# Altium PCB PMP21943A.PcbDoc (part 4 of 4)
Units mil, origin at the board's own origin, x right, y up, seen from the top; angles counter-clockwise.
Board outline 5100 x 3900 mil, 8 copper layers (Top Layer, Signal Layer 1, Signal Layer 2, Signal Layer 3, Signal Layer 4, Signal Layer 5, Signal Layer 6, Bottom Layer), stack 61.6 mil thick; 371 components, 163 nets, 967 pads, 1147 vias.
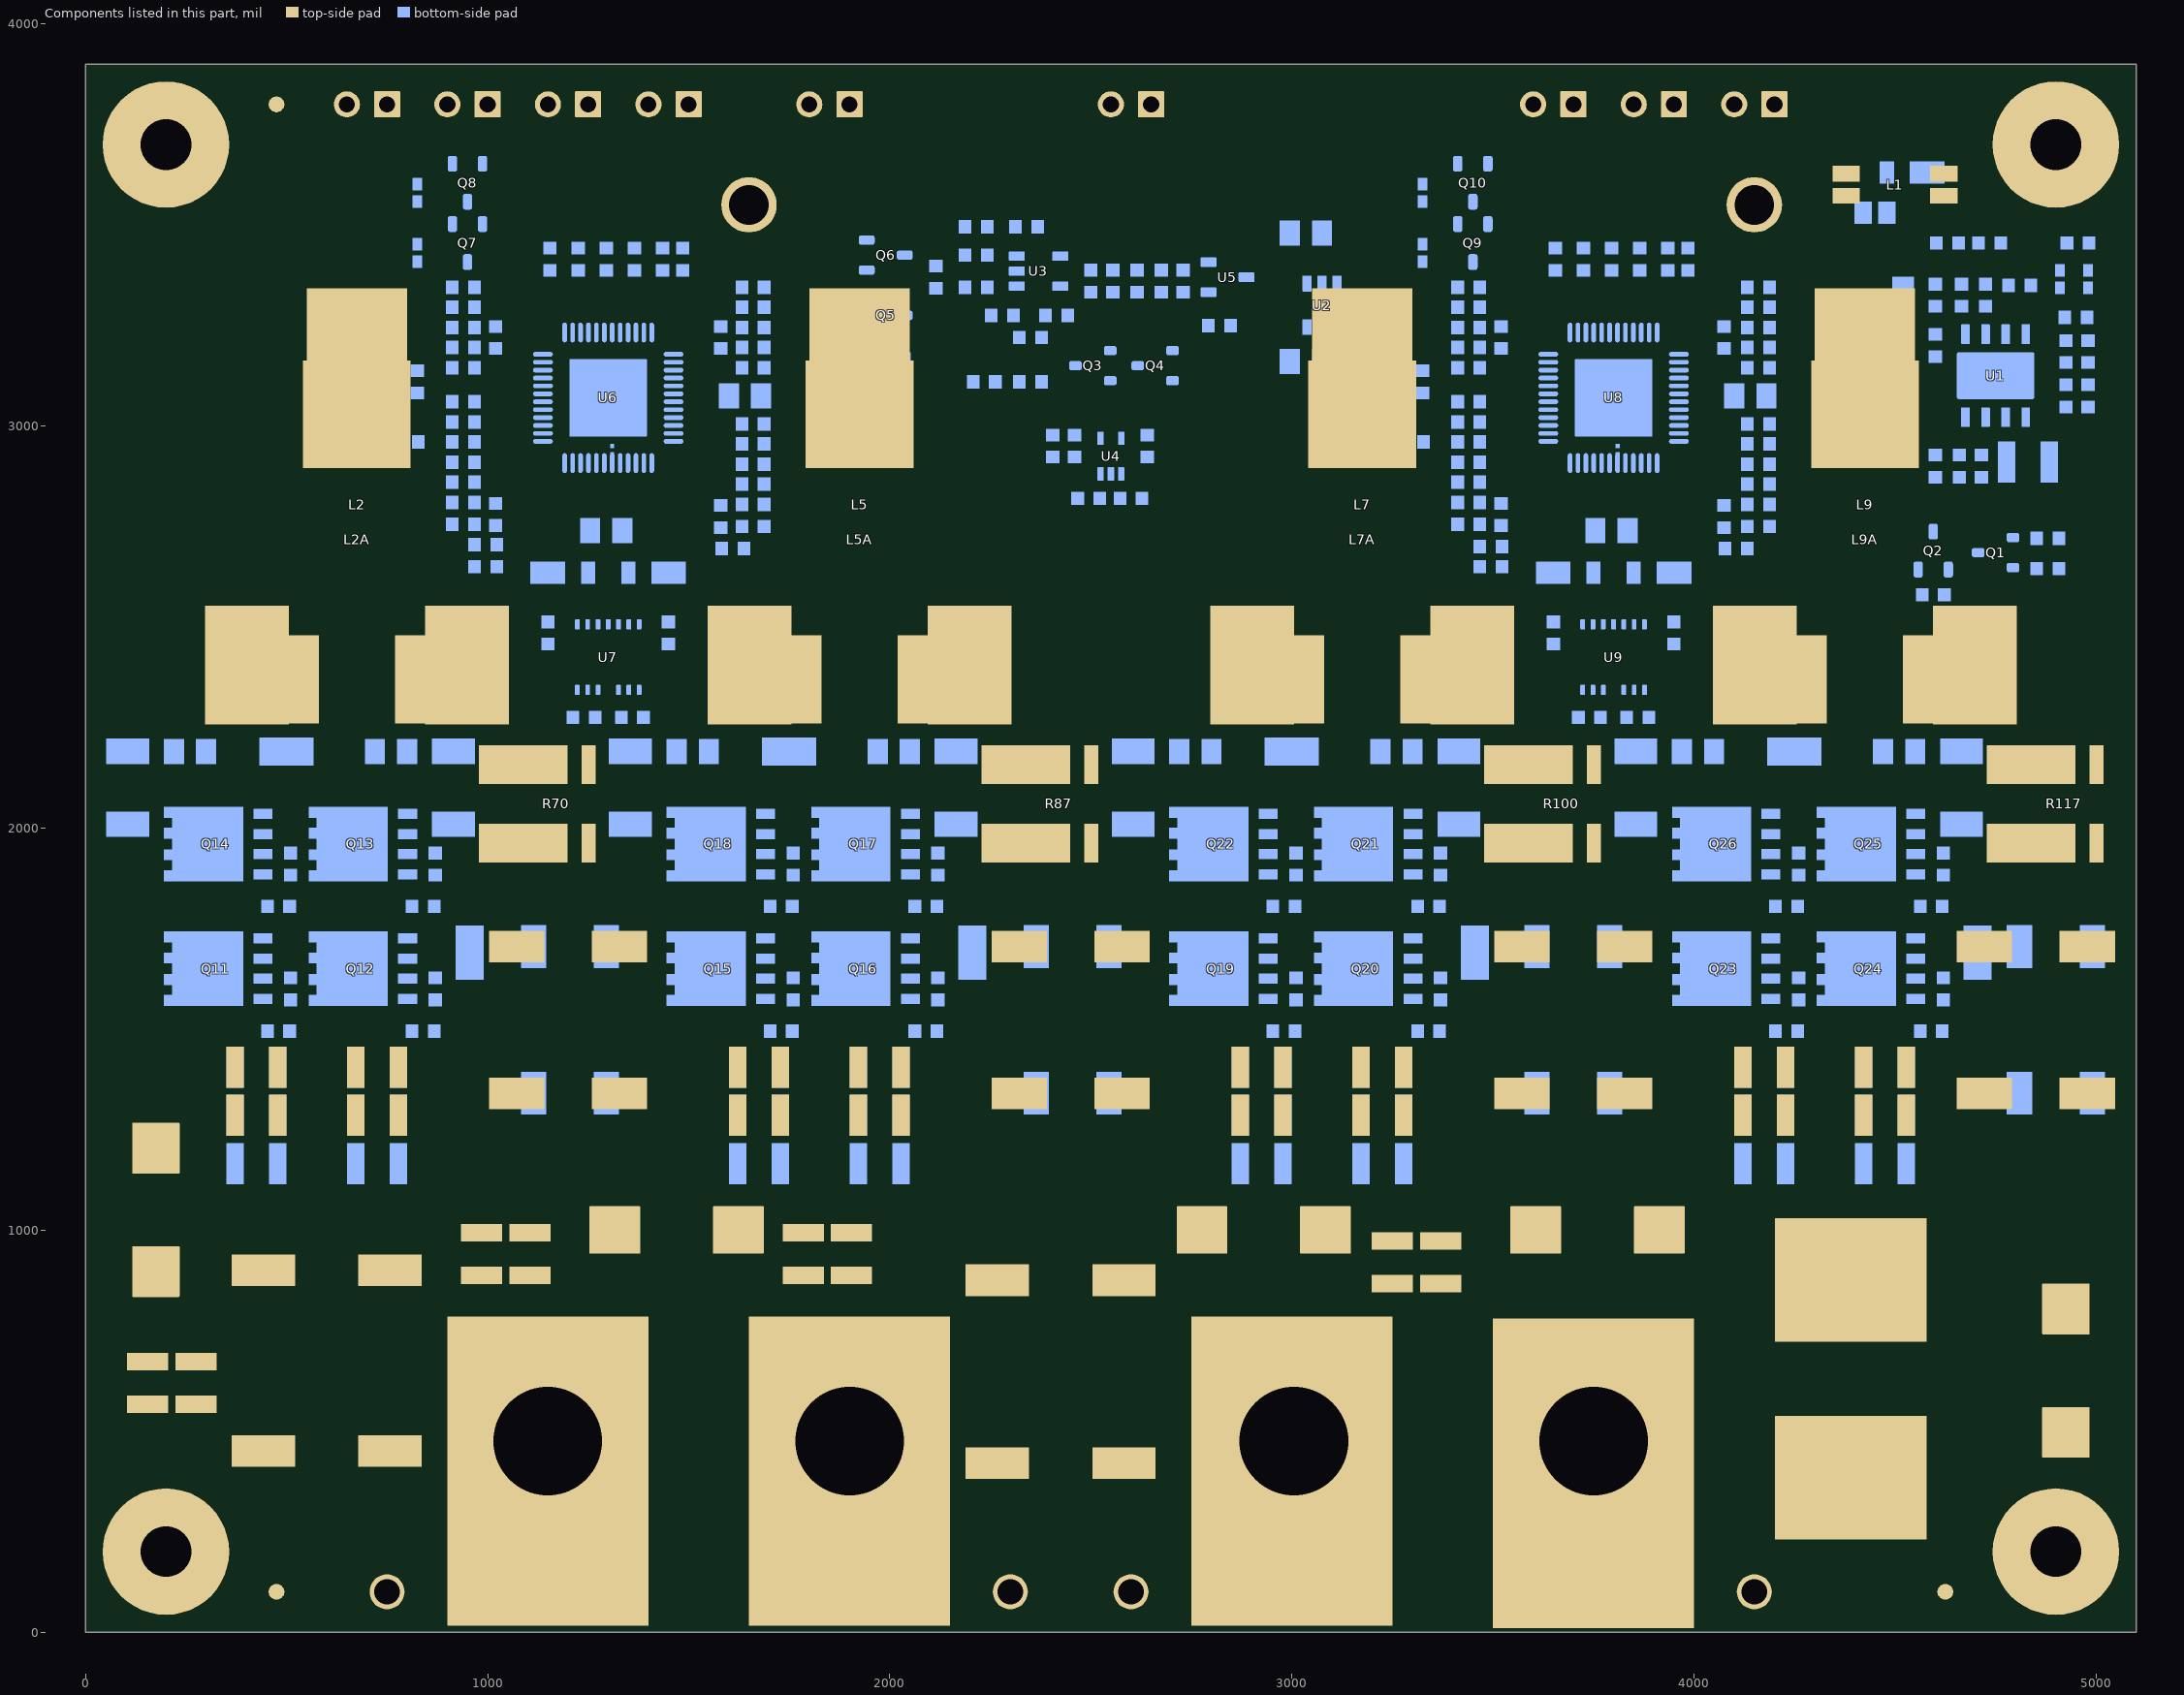
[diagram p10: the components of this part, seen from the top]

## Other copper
Top Layer:
  rectangle net -VIN: 4650,3065 4850,3190
  rectangle net NetC116_2: 4905,1645 5050,1765
  rectangle net NetC115_2: 4905,1280 5050,1400
  rectangle net NetC108_2: 3755,1645 3900,1765
  rectangle net NetC107_2: 3755,1280 3900,1400
  rectangle net NetC82_2: 2505,1645 2650,1765
  rectangle net NetC81_2: 2505,1280 2650,1400
  rectangle net NetC73_2: 1255,1645 1400,1765
  rectangle net NetC72_2: 1255,1280 1400,1400
  region net NetC74_2: 4700,350 4750,400 5050,400 5050,625 4150,625 4150,900 3470,900 3470,50 4530,50 4530,145 4585,200 4700,200
  region net -VIN: 5050,1030 5050,670 4640,670 4640,1030
  region net +VOUT: 2495,1070 2665,1070 2665,250 2495,250
  region net PGND: 2510,50 2510,200 2700,200 2700,900 3430,900 3430,50
  region net +VOUT: 3790,1065 2935,1065 2935,935 3155,935 3465,935 3790,935
  region net PGND: 3315,1750 3370,1750 3385,1735 3385,1715 3370,1700 3315,1700 3315,1495 3460,1495 3460,1100 3900,1100 3900,1250 3710,1250 3710,1430 3900,1430 3900,1615 3710,1615 3710,1795 3900,1795 3900,1885 3710,1885 3710,2070 3315,2070
  region net PGND: 2935,1105 3215,1105 3215,1460 2935,1460
  region net PGND: 2065,1750 2120,1750 2135,1735 2135,1715 2120,1700 2065,1700 2065,1495 2210,1495 2210,1065 2005,1065 2005,790 1550,790 1550,50 2460,50 2460,1100 2650,1100 2650,1250 2460,1250 2460,1430 2650,1430 2650,1615 2460,1615 2460,1795 2650,1795 2650,1885 2460,1885 2460,2070 2065,2070
  region net +VOUT: 1395,910 1965,910 1965,825 1510,825 1510,50 1395,50
  region net PGND: 1685,1095 1725,1095 1725,940 1965,940 1965,1460 1685,1460
  region net +VOUT: 570,50 570,310 890,310 890,920 1245,920 1245,1065 1400,1065 1400,50
  region net PGND: 50,600 330,600 330,400 50,400
  region net +VOUT: 515,195 400,195 400,310 360,350 360,625 50,625 50,965 560,965 560,350 600,310 600,110
  region net PGND: 810,1750 870,1750 885,1735 885,1715 870,1700 810,1700 810,1495 955,1495 955,1100 845,1100 845,960 1205,960 1205,1100 1400,1100 1400,1250 1205,1250 1205,1430 1400,1430 1400,1615 1205,1615 1205,1795 1400,1795 1400,1885 1205,1885 1205,2080 810,2080
  region net PGND: 600,400 650,350 850,350 850,1100 600,1100
  region net -VIN: 750,1460 925,1460 925,1130 750,1130
  region net PGND: 435,1460 715,1460 715,995 435,995
  region net NetC67_1: 50,2055 395,2055 395,1845 380,1830 380,1775 400,1755 400,1535 380,1515 380,1465 400,1445 400,995 50,995
  region net SW1_1: 755,1845 740,1830 740,1775 755,1760 755,1525 440,1525 440,2085 285,2085 285,2565 720,2565 720,2070 755,2070
  region net NetL2_2: 1165,2320 1140,2345 1140,2565 760,2565 760,2100 1210,2100 1210,2320
  region net NetL5_2: 2415,2320 2390,2345 2390,2565 2010,2565 2010,2100 2460,2100 2460,2320
  region net SW2_1: 2005,1845 1990,1830 1990,1775 2005,1760 2005,1525 1690,1525 1690,2085 1535,2085 1535,2565 1970,2565 1970,2070 2005,2070
  region net NetL7_2: 3665,2320 3640,2345 3640,2565 3260,2565 3260,2100 3710,2100 3710,2320
  region net SW1_2: 3255,1845 3240,1830 3240,1775 3255,1760 3255,1525 2940,1525 2940,2085 2785,2085 2785,2565 3220,2565 3220,2070 3255,2070
  region net NetL9_2: 4915,2320 4890,2345 4890,2565 4510,2565 4510,2100 4960,2100 4960,2320
  region net SW2_2: 4505,1845 4490,1830 4490,1775 4505,1760 4505,1525 4190,1525 4190,2085 4035,2085 4035,2565 4470,2565 4470,2070 4505,2070
  region net NetC92_1: 1440,2055 1645,2055 1645,1845 1630,1830 1630,1775 1645,1760 1645,1530 1630,1515 1630,1465 1650,1445 1650,940 1440,940
  region net NetC102_1: 2700,2055 2895,2055 2895,1845 2880,1830 2880,1775 2895,1760 2895,1530 2880,1515 2880,1465 2900,1445 2900,935 2700,935
  region net NetC126_1: 3940,1065 3830,1065 3830,935 4150,935 4150,1445 4130,1465 4130,1515 4145,1530 4145,1760 4130,1775 4130,1830 4145,1845 4145,2055 3940,2055
  region net -VIN: 2005,1460 2180,1460 2180,1130 2005,1130
  region net -VIN: 3255,1460 3430,1460 3430,1130 3255,1130
  region net PGND: 4185,670 4600,670 4600,1030 4465,1030 4465,1460 4185,1460
  region net PGND: 4565,1750 4620,1750 4635,1735 4635,1715 4620,1700 4565,1700 4565,1495 4710,1495 4710,1065 5050,1065 5050,1250 4875,1250 4875,1430 5050,1430 5050,1615 4875,1615 4875,1795 5050,1795 5050,1885 4950,1885 4950,2065 4885,2065 4880,2070 4565,2070
  region net -VIN: 4680,1410 4620,1410 4620,1270 4680,1270 4680,1065 4505,1065 4505,1460 4680,1460
  text ".Layer_Name" at 77,-858.49 h60
Signal Layer 1:
  rectangle net SW2_2: 4315,1555 4505,1745
  rectangle net SW2_2: 4315,1865 4505,2055
  rectangle net NetC126_1: 3955,1555 4145,1745
  rectangle net NetC126_1: 3955,1865 4145,2055
  rectangle net SW1_2: 3065,1555 3255,1745
  rectangle net SW1_2: 3065,1865 3255,2055
  rectangle net NetC102_1: 2705,1555 2895,1745
  rectangle net NetC102_1: 2705,1865 2895,2055
  rectangle net SW2_1: 1815,1555 2005,1745
  rectangle net NetC92_1: 1455,1555 1645,1745
  rectangle net SW2_1: 1815,1865 2005,2055
  rectangle net NetC92_1: 1455,1865 1645,2055
  rectangle net SW1_1: 565,1555 755,1745
  rectangle net SW1_1: 565,1865 755,2055
  rectangle net NetC67_1: 205,1555 395,1745
  rectangle net NetC67_1: 205,1865 395,2055
  text ".Layer_Name" at 75,-855 h60
Signal Layer 2:
  rectangle net NetC67_1: 205,1865 395,2055
  rectangle net NetC67_1: 205,1555 395,1745
  rectangle net SW1_1: 565,1865 755,2055
  rectangle net SW1_1: 565,1555 755,1745
  rectangle net NetC92_1: 1455,1865 1645,2055
  rectangle net NetC92_1: 1455,1555 1645,1745
  rectangle net SW2_1: 1815,1865 2005,2055
  rectangle net SW2_1: 1815,1555 2005,1745
  rectangle net NetC102_1: 2705,1865 2895,2055
  rectangle net NetC102_1: 2705,1555 2895,1745
  rectangle net SW1_2: 3065,1865 3255,2055
  rectangle net SW1_2: 3065,1555 3255,1745
  rectangle net NetC126_1: 3955,1865 4145,2055
  rectangle net NetC126_1: 3955,1555 4145,1745
  rectangle net SW2_2: 4315,1865 4505,2055
  rectangle net SW2_2: 4315,1555 4505,1745
  text ".Layer_Name" at 75,-855 h60
Signal Layer 3:
  rectangle net NetC102_1: 2705,1555 2895,1745
  rectangle net NetC102_1: 2705,1865 2895,2055
  rectangle net NetC92_1: 1455,1555 1645,1745
  rectangle net NetC92_1: 1455,1865 1645,2055
  rectangle net NetC67_1: 205,1555 395,1745
  rectangle net NetC67_1: 205,1865 395,2055
  region net SW2_2: 4330,2470 4505,2295 4505,1845 4490,1830 4490,1775 4505,1760 4505,1525 4280,1525 4280,2205 4215,2270 4070,2270 4070,2470
  region net SW1_2: 3080,2470 3255,2295 3255,1845 3240,1830 3240,1775 3255,1760 3255,1525 3030,1525 3030,2205 2965,2270 2820,2270 2820,2470
  region net SW2_1: 1830,2470 2005,2295 2005,1845 1990,1830 1990,1775 2005,1760 2005,1525 1780,1525 1780,2205 1715,2270 1570,2270 1570,2470
  region net SW1_1: 580,2470 755,2295 755,1845 740,1830 740,1775 755,1760 755,1525 530,1525 530,2205 465,2270 320,2270 320,2470
  text ".Layer_Name" at 75,-855 h60
Signal Layer 4:
  rectangle net NetC67_1: 205,1555 395,1745
  rectangle net NetC67_1: 205,1865 395,2055
  rectangle net NetC92_1: 1455,1555 1645,1745
  rectangle net NetC92_1: 1455,1865 1645,2055
  rectangle net NetC102_1: 2705,1555 2895,1745
  rectangle net NetC102_1: 2705,1865 2895,2055
  region net SW1_1: 580,2470 755,2295 755,1845 740,1830 740,1775 755,1760 755,1525 530,1525 530,2205 465,2270 320,2270 320,2470
  region net SW2_1: 1830,2470 2005,2295 2005,1845 1990,1830 1990,1775 2005,1760 2005,1525 1780,1525 1780,2205 1715,2270 1570,2270 1570,2470
  region net SW1_2: 3080,2470 3255,2295 3255,1845 3240,1830 3240,1775 3255,1760 3255,1525 3030,1525 3030,2205 2965,2270 2820,2270 2820,2470
  region net SW2_2: 4330,2470 4505,2295 4505,1845 4490,1830 4490,1775 4505,1760 4505,1525 4280,1525 4280,2205 4215,2270 4070,2270 4070,2470
Signal Layer 5:
  rectangle net NetC67_1: 205,1865 395,2055
  rectangle net NetC67_1: 205,1555 395,1745
  rectangle net SW1_1: 565,1865 755,2055
  rectangle net SW1_1: 565,1555 755,1745
  rectangle net NetC92_1: 1455,1865 1645,2055
  rectangle net NetC92_1: 1455,1555 1645,1745
  rectangle net SW2_1: 1815,1865 2005,2055
  rectangle net SW2_1: 1815,1555 2005,1745
  rectangle net NetC102_1: 2705,1865 2895,2055
  rectangle net NetC102_1: 2705,1555 2895,1745
  rectangle net SW1_2: 3065,1865 3255,2055
  rectangle net SW1_2: 3065,1555 3255,1745
  rectangle net NetC126_1: 3955,1865 4145,2055
  rectangle net NetC126_1: 3955,1555 4145,1745
  rectangle net SW2_2: 4315,1865 4505,2055
  rectangle net SW2_2: 4315,1555 4505,1745
  region: 910,3542.56
  text ".Layer_Name" at 75,-855 h60
  text ".layer_Name" at 80,-860 h60
Signal Layer 6:
  rectangle net NetC126_1: 3955,1865 4145,2055
  rectangle net NetC126_1: 3955,1555 4145,1745
  rectangle net SW2_2: 4315,1865 4505,2055
  rectangle net SW2_2: 4315,1555 4505,1745
  rectangle net NetC102_1: 2705,1865 2895,2055
  rectangle net NetC102_1: 2705,1555 2895,1745
  rectangle net SW1_2: 3065,1865 3255,2055
  rectangle net SW1_2: 3065,1555 3255,1745
  rectangle net NetC92_1: 1455,1865 1645,2055
  rectangle net NetC92_1: 1455,1555 1645,1745
  rectangle net SW2_1: 1815,1865 2005,2055
  rectangle net SW2_1: 1815,1555 2005,1745
  rectangle net NetC67_1: 205,1865 395,2055
  rectangle net NetC67_1: 205,1555 395,1745
  rectangle net SW1_1: 565,1865 755,2055
  rectangle net SW1_1: 565,1555 755,1745
  text ".layer_Name" at 80,-860 h60
Bottom Layer:
  rectangle net AGND: 1280,2950 1340,2975
  rectangle net AGND: 3780,2950 3840,2975
  rectangle net NetC116_2: 4905,1645 5030,1765
  rectangle net NetC115_2: 4905,1280 5030,1400
  rectangle net NetC108_2: 3755,1645 3880,1765
  rectangle net NetC107_2: 3755,1280 3880,1400
  rectangle net NetC82_2: 2505,1645 2630,1765
  rectangle net NetC81_2: 2505,1280 2630,1400
  rectangle net NetC73_2: 1255,1645 1380,1765
  rectangle net NetC72_2: 1255,1280 1380,1400
  region net SW2_2: 4500,1840 4490,1830 4490,1775 4500,1765 4500,1525 4305,1525 4305,1610 4170,1610 4170,1770 4305,1770 4305,1920 4170,1920 4170,2085 4025,2085 4025,2475 4500,2475
  region net NetC126_1: 3800,1925 3920,1925 3920,1065 4150,1065 4150,1445 4130,1465 4130,1515 4150,1535 4150,1755 4130,1775 4130,1830 4145,1845 4145,2055 3800,2055
  region net NetC102_1: 2550,1925 2670,1925 2670,1065 2900,1065 2900,1445 2880,1465 2880,1515 2900,1535 2900,1755 2880,1775 2880,1830 2895,1845 2895,2055 2550,2055
  region net -VIN: 3280,2080 3710,2080 3710,1105 3255,1105 3255,1455 3415,1455 3415,1610 3280,1610 3280,1770 3415,1770 3415,1920 3280,1920
  region net SW1_2: 3250,1840 3240,1830 3240,1775 3250,1765 3250,1525 3055,1525 3055,1610 2920,1610 2920,1770 3055,1770 3055,1920 2920,1920 2920,2085 2775,2085 2775,2475 3250,2475
  region net PGND: 2935,1105 3215,1105 3215,1455 2935,1455
  region net -VIN: 2030,2080 2460,2080 2460,1105 2005,1105 2005,1455 2165,1455 2165,1610 2030,1610 2030,1770 2165,1770 2165,1920 2030,1920
  region net NetC92_1: 1300,1925 1420,1925 1420,1065 1650,1065 1650,1445 1630,1465 1630,1515 1650,1535 1650,1755 1630,1775 1630,1830 1645,1845 1645,2055 1300,2055
  region net SW2_1: 2000,1840 1990,1830 1990,1775 2000,1765 2000,1525 1805,1525 1805,1610 1670,1610 1670,1770 1805,1770 1805,1920 1670,1920 1670,2085 1525,2085 1525,2475 2000,2475
  region net PGND: 1685,1455 1965,1455 1965,1065 1685,1065
  region net PGND: 50,600 330,600 330,400 50,400
  region net NetC67_1: 50,2055 395,2055 395,1845 380,1830 380,1775 400,1755 400,1535 380,1515 380,1465 400,1445 400,995 50,995
  region net PGND: 435,1455 715,1455 715,1050 435,1050
  region net -VIN: 775,2080 1205,2080 1205,1105 750,1105 750,1455 910,1455 910,1610 775,1610 775,1770 910,1770 910,1920 775,1920
  region net SW1_1: 750,1840 740,1830 740,1775 750,1765 750,1525 555,1525 555,1610 420,1610 420,1770 555,1770 555,1920 420,1920 420,2085 275,2085 275,2475 750,2475
  region net PGND: 4185,1105 4465,1105 4465,1455 4185,1455
  region net -VIN: 4530,2080 4875,2080 4875,1065 4505,1065 4505,1455 4665,1455 4665,1610 4530,1610 4530,1770 4665,1770 4665,1920 4530,1920
  text "MADE IN U.S." at 4695,285 h60
  text "UL94V-0" at 4695,175 h60
  text ".CopyrightYear" at 4605,65 h60
  text "©" at 4700,61.48 h105
  text ".Layer_Name" at 77,-858.49 h60

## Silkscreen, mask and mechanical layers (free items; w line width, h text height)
Top Overlay:
  region: 3030,3620 2730,3620 2730,3520 3030,3520
  text ".PRJ_Number" at 2090,3540 h60
  text ".PCB_Rev" at 2585,3540 h60
  text "-" at 2665,3535 h60
  text ".Layer_Name" at 77,-858.49 h60
Bottom Overlay:
  text ".Layer_Name" at 77,-858.49 h60
Top Paste:
  text ".Layer_Name" at 77,-858.49 h60
Bottom Paste:
  text ".Layer_Name" at 77,-858.49 h60
Top Solder:
  text ".Layer_Name" at 77,-858.49 h60
  text ".Layer_Name" at 77,-858.49 h60
Bottom Solder:
  text ".Layer_Name" at 77,-858.49 h60
Drill Guide:
  text ".Layer_Name" at 77,-858.49 h60
M1 Board Outline:
  the board outline again, w10
  text ".Layer_Name" at 77,-858.49 h60
M2 Board Dimensions:
  rectangle: -375,-400 0,-275
  rectangle: -500,-275 -375,-150
  lines w7: -500,-275 500,-275 ; -375,-400 -375,-150 ; -250,-400 -250,-150 ; 0,-400 0,-150 ; 250,-400 250,-150 ; -500,-400 -500,-150 500,-150 500,-400 -500,-400
  text ".Layer_Name" at 77,-858.49 h60
M3 3D STEP Top:
  text ".Layer_Name" at 77,-858.49 h60
M4 3D STEP Bottom:
  text ".Layer_Name" at 77,-858.49 h60
M5 Assembly Top:
  lines w10: -792,-930.17 5808,-930.17 ; -792,-726.83 5810,-726.83 ; -792,-523.5 -792,-1133.5 3213,-1133.5 5810,-1133.5 5810,-523.5 -791.5,-523.5 -791.5,-1133.5 784,-1133.5 ; 1673,-1133.5 1673,-523.5 ; 2940,-726.83 2940,-523.5 ; 3780,-726.83 3780,-523.5 ; 4402,-1140 4402,-937.17
  text "COMPONENTS MARKED 'DNP' SHOULD NOT BE POPULATED." at 653.5,-318.5 h60
  text "ASSEMBLY VARIANT:" at 653,-434 h60
  text ".VariantName" at 1689,-434 h60
  text "PCB VIEWED FROM TOP SIDE" at -728.5,-655.67 h60
  text "BOARD #:" at 1748,-655.67 h60
  text ".PRJ_Number" at 2293.5,-655.67 h60
  text "REV:" at 3138,-655.67 h60
  text ".PCB_Rev" at 3429.5,-655.67 h60
  text ".VersionControl_RevNumber" at 4482,-655.67 h60
  text "SVN REV:" at 3213.19,-696.26 h60
  text "PLOT NAME =" at -728.5,-1064.34 h60
  text ".plot_File_Name" at 77,-1064.34 h60
  text "GENERATED    :" at 1750,-1064.34 h60
  text ".Print_Date" at 2619.5,-1064.34 h60
  text ".Print_Time" at 3348.5,-1064.34 h60
  text "TEXAS INSTRUMENTS" at 4613,-1064.34 h60
M6 Assembly Bottom:
  lines w10: -792.5,-727.33 5809.5,-727.33 ; -790.5,-930.67 5809.5,-930.67 ; 615.5,-1140.5 615.5,-937.67 ; 1237.5,-727.33 1237.5,-524 ; 2077.5,-727.33 2077.5,-524 ; 3344.5,-1134 3344.5,-524 ; 4233.5,-1134 5809,-1134 5809,-524 -792.5,-524 -792.5,-1134 1804.5,-1134 5809.5,-1134 5809.5,-524
  text "COMPONENTS MARKED 'DNP' SHOULD NOT BE POPULATED." at 5602,-318 h60
  text ".VariantName" at 4558,-434 h60
  text "ASSEMBLY VARIANT:" at 5597,-434 h60
  text ".VersionControl_RevNumber" at 535.5,-656.17 h60
  text "SVN REV:" at 1041.5,-656.17 h60
  text ".PCB_Rev" at 1588,-656.17 h60
  text "REV:" at 1879.5,-656.17 h60
  text ".PRJ_Number" at 2724,-656.17 h60
  text "BOARD #:" at 3269.5,-656.17 h60
  text "PCB VIEWED FROM BOTTOM SIDE" at 5746,-656.17 h60
  text "TEXAS INSTRUMENTS" at 404.5,-1064.84 h60
  text ".Print_Time" at 1669,-1064.84 h60
  text ".Print_Date" at 2398,-1064.84 h60
  text "GENERATED    :" at 3267.5,-1064.84 h60
  text ".plot_File_Name" at 4940.5,-1064.84 h60
  text "PLOT NAME =" at 5746,-1064.84 h60
M9 Title Sheet:
  drawing of 57 lines, arcs and shapes, not listed
  text "1" at 239.84,8036.5 h70
  text "2" at 2735.5,8036.5 h70
  text "3" at 5224.84,8036.5 h70
  text "4" at 7731.51,8036.5 h70
  text "5" at 10230.5,8036.5 h70
  text "6" at 12735.5,8036.5 h70
  text "A" at -916.5,6893.5 h70
  text "A" at 13883.5,6893.5 h70
  text "B" at -916.5,4513.5 h70
  text "B" at 13883.5,4513.5 h70
  text "C" at -916.5,2138.5 h70
  text "C" at 13883.5,2138.5 h70
  text "PROJECT TITLE:" at 10843.5,277.5 h45
  text ".PRJ_Title" at 10893.5,144.17 h70
  text "DESIGNED FOR:" at 10843.5,-23.5 h45
  text ".PRJ_Customer" at 10893.5,-163.5 h70
  text "D" at -916.5,-231.5 h70
  text "D" at 13883.5,-231.5 h70
  text "FILE NAME:" at 10843.5,-323.5 h45
  text ".PCB_File_Name_No_Path" at 10893.5,-443.5 h70
  text "Texas Instruments (TI) and/or its licensors do not warrant the accuracy or completeness of this specification" at 5874,-605.34 h45
  text "ENGINEER:" at 10843.5,-613.5 h45
  text "LAYOUT BY:" at 12348.5,-613.5 h45
  text "or any information contained therein. TI and/or its licensors do not warrant that this design will meet" at 5829.01,-718 h45
  text ".PRJ_Engineer" at 10893.5,-768.49 h70
  text ".PCB_Layout" at 12399,-768.49 h70
  text "the specifications, will be suitable for your application or fit for any particular purpose, or will operate in" at 5829.01,-830.67 h45
  text ".Layer_Name" at 77,-858.49 h60
  text "ALTIUM DESIGNER VERSION:" at 12348.5,-923.5 h45
  text "an implementation. TI and/or its licensors do not warrant that the design is production worthy. You should" at 5829.01,-943.33 h45
  text "completely validate and test your design implementation to confirm the system functionality for your application." at 5874,-1056 h45
  text ".print_Scale" at 10893.5,-1056.83 h70
  text ".Application_BuildNumber" at 12399,-1056.83 h70
  text "1" at 239.84,-1263.5 h70
  text "2" at 2735.5,-1263.5 h70
  text "3" at 5224.84,-1263.5 h70
  text "4" at 7731.51,-1263.5 h70
  text "5" at 10230.5,-1263.5 h70
  text "6" at 12735.5,-1263.5 h70
M10 Fab Notes:
  drawing of 185 lines, arcs and shapes, not listed
  text "DESIGN INFORMATION" at 11881.02,5910 h60
  text "MIN. TRACK WIDTH:" at 11236.46,5730 h60
  text "8" at 12332.7,5730 h60
  text "MIL" at 12487.46,5730 h60
  text "MIN. CLEARANCE:" at 11236.46,5598 h60
  text "0.2" at 12272.7,5598 h60
  text "mm" at 12487.46,5598 h60
  text "MIN. VIA PAD SIZE:" at 11236.46,5466 h60
  text "20" at 12302.71,5466 h60
  text "MIL" at 12487.46,5466 h60
  text "0.05mm (2MIL)" at 11931.46,5324.29 h60
  text "MINIMUM ANNULAR RING" at 10907.23,5320 h60
  text "EXTERNAL" at 12639.46,5320 h60
  text "PER" at 11107.23,5202 h60
  text "IPC-D-275 CLASS 2 LEVEL C" at 11327.23,5202 h60
  text "MIL, HOLES" at 12815.46,5089.71 h60
  text "+/-" at 12423,5089 h60
  text "+/-" at 13277,5089 h60
  text "REGISTRATION TOLERANCES:" at 10907.23,5084 h60
  text "METAL" at 12107,5084 h60
  text "5" at 12683.2,5084 h60
  text "3" at 13516.2,5084 h60
  text "MIL" at 13632.46,5084 h60
  text "MATERIAL:" at 10832.46,4874.54 h60
  text "FR-4 High Tg" at 11818.9,4734.21 h60
  text "FR-408" at 11253.46,4725.64 h60
  text "X" at 11665.46,4725.64 h60
  text "OTHER" at 12741.46,4725.64 h60
  text "62 MIL (1.6mm) +/-10%" at 11573.56,4562.92 h60
  text "THICKNESS:" at 10907.23,4558.64 h60
  text "X" at 11445.4,4558.64 h60
  text "OTHER" at 12858.46,4558.64 h60
  text "TOLERANCE:" at 10907.23,4400.64 h60
  text "X" at 11746.53,4400.64 h60
  text "ANSI IPC-6012 TYPE 3 CLASS 2" at 11933.48,4400.64 h60
  text "OTHER +/-" at 11933.46,4244.64 h60
  text "BOW & TWIST:" at 10907.23,4087.64 h60
  text "X" at 11746.53,4087.64 h60
  text "ANSI IPC-6012 TYPE 3 CLASS 2" at 11933.48,4087.64 h60
  text "OTHER +/-" at 11933.46,3929.13 h60
  text "DRILLING:" at 10832.46,3790.64 h60
  text "REFERENCE:" at 10907.23,3673.64 h60
  text "X" at 11555.46,3673.64 h60
  text "AS SHOWN" at 11742.46,3673.64 h60
  text "X" at 12456.46,3673.64 h60
  text "NC_DRILL FILES" at 12593.46,3673.64 h60
  text "PTH MIN COPPER THICKNESS:" at 10907.23,3515.64 h60
  text "X" at 12257.46,3515.64 h60
  text "1MIL" at 12394.46,3515.64 h60
  text "OTHER" at 12891.46,3515.64 h60
  text "BOARD FINISH:" at 10832.46,3356.64 h60
  text "SILKSCREEN:" at 10987.68,3238.64 h60
  text "X" at 11936.46,3238.64 h60
  text "TOP" at 12062.46,3238.64 h60
  text "X" at 12446.46,3238.64 h60
  text "BOTTOM" at 12573.46,3238.64 h60
  text "SILKSCREEN COLOR:" at 10987.68,3071.64 h60
  text "X" at 11935.42,3071.64 h60
  text "WHITE" at 12062.46,3071.64 h60
  text "OTHER" at 12573.46,3071.64 h60
  text "SOLDER RESIST COLOR:" at 10987.68,2901.64 h60
  text "X" at 11555.42,2742.44 h60
  text "GREEN" at 11682.46,2742.44 h60
  text "BLUE" at 12273.46,2742.44 h60
  text "OTHER" at 12811.46,2742.44 h60
  text "IMMERSION GOLD (ENIG)" at 11893.46,2553.92 h60
  text "ENEPIG" at 13231,2550.64 h60
  text "SURFACE FINISH:" at 10832.46,2549.64 h60
  text "X" at 11705,2545 h60
  text "IMM. TIN/SILVER OR EQUIV" at 11162,2392.64 h60
  text "OTHER" at 12593.46,2392.64 h60
  text "ARRAY/PANEL:" at 10832.46,2213.64 h60
  text "X" at 11705,2210 h60
  text "CUT AND TRIM PER MECH LAYER 1" at 11893.46,2209.35 h60
  text "N.C. ROUTE" at 11893.46,2057.64 h60
  text "V. SCORE" at 12759.46,2057.64 h60
  text "CERTIFICATION:" at 10832.46,1920.64 h60
  text "MATERIALS AND WORKMANSHIP FOR ALL PCBS" at 11557.46,1920.64 h60
  text "TO MEET OR EXCEED THE REQUIREMENTS OF:" at 11557.46,1822.64 h60
  text "X" at 11183.96,1686.13 h60
  text "ANSI IPC-A-600F CLASS ->" at 11322.96,1686.13 h60
  text "X" at 12962.02,1686.13 h60
  text "2" at 13080.96,1686.14 h60
  text "1" at 12765.96,1684.64 h60
  text "3" at 13434.96,1684.64 h60
  text "X" at 11186.02,1526.64 h60
  text "UL 94V-0" at 11322.96,1526.64 h60
  text "X" at 11998.02,1526.64 h60
  text "RoHS" at 12134.96,1526.64 h60
  text "OTHER" at 12779.36,1526.64 h60
  text "PER ORDER" at 13176.42,1526.64 h60
  text "ADDITIONAL REQUIREMENTS:" at 10832.46,1385.64 h60
  text "MICROSECTION:" at 10907.23,1270.64 h60
  text "YES" at 11812.96,1270.64 h60
  text "REQUIRED" at 12674.46,1114.49 h60
  text "BARE BOARD ELEC. TEST:" at 10907.23,1111.64 h60
  text "NONE" at 12212.96,1111.64 h60
  text "X" at 12547.46,1111.64 h60
  text "PER ORDER" at 13266.46,1111.64 h60
  text "MANUFACTURER'S UL:" at 10907.23,954.64 h60
  text "RAIL" at 12072.96,950.35 h60
  text "METAL" at 12564.77,950.35 h60
  text "X" at 12940,950 h60
  text "SILK" at 13076.46,950.35 h60
  text ".Layer_Name" at 77,-858.49 h60
M11 Gerber Information:
  lines w10: -792,-930.17 5808,-930.17 ; -792,-726.83 5810,-726.83 ; -792,-523.5 -792,-1133.5 3213,-1133.5 5810,-1133.5 5810,-523.5 -791.5,-523.5 -791.5,-1133.5 784,-1133.5 ; 1673,-1133.5 1673,-523.5 ; 2940,-726.83 2940,-523.5 ; 3780,-726.83 3780,-523.5 ; 4402,-1140 4402,-937.17
  text "ALL ARTWORK VIEWED FROM TOP SIDE" at -728.5,-655.67 h60
  text "BOARD #:" at 1748,-655.67 h60
  text ".PRJ_Number" at 2293.5,-655.67 h60
  text "REV:" at 3138,-655.67 h60
  text ".PCB_Rev" at 3429.5,-655.67 h60
  text ".VersionControl_RevNumber" at 4482,-655.67 h60
  text "SVN REV:" at 3213.19,-696.26 h60
  text "LAYER NAME =" at -728.5,-858.49 h60
  text "PLOT NAME =" at -728.5,-1064.34 h60
  text ".plot_File_Name" at 77,-1064.34 h60
  text "GENERATED    :" at 1750,-1064.34 h60
  text ".Print_Date" at 2619.5,-1064.34 h60
  text ".Print_Time" at 3348.5,-1064.34 h60
  text "TEXAS INSTRUMENTS" at 4613,-1064.34 h60
M12 Stackup:
  drawing of 503 lines, arcs and shapes, not listed
  text "Layer" at 5562.59,7827.5 h60
  text "Name" at 5972.5,7827.5 h60
  text "Material" at 6912.24,7827.5 h60
  text "Thickness" at 7772.01,7827.5 h60
  text "Constant" at 8421.84,7827.5 h60
  text "Board Layer Stack" at 8991.7,7827.5 h60
  text "1" at 5562.59,7707.5 h60
  text "Top Overlay" at 5972.5,7707.5 h60
  text "2" at 5562.59,7587.5 h60
  text "Top Solder" at 5972.5,7587.5 h60
  text "Solder Resist" at 6912.24,7587.5 h60
  text "0.40mil" at 7772.01,7587.5 h60
  text "3.5" at 8421.84,7587.5 h60
  text "3" at 5562.59,7467.5 h60
  text "Top Layer" at 5972.5,7467.5 h60
  text "Copper" at 6912.24,7467.5 h60
  text "2.80mil" at 7772.01,7467.5 h60
  text "4" at 5562.59,7347.5 h60
  text "Dielectric1" at 5972.5,7347.5 h60
  text "FR-4" at 6912.24,7347.5 h60
  text "5.60mil" at 7772.01,7347.5 h60
  text "4.8" at 8421.84,7347.5 h60
  text "5" at 5562.59,7227.5 h60
  text "Signal Layer 1" at 5972.5,7227.5 h60
  text "Copper" at 6912.24,7227.5 h60
  text "2.80mil" at 7772.01,7227.5 h60
  text "6" at 5562.59,7107.5 h60
  text "Dielectric 2" at 5972.5,7107.5 h60
  text "FR-4" at 6912.24,7107.5 h60
  text "5.60mil" at 7772.01,7107.5 h60
  text "4.2" at 8421.84,7107.5 h60
  text "7" at 5562.59,6987.5 h60
  text "Signal Layer 2" at 5972.5,6987.5 h60
  text "Copper" at 6912.24,6987.5 h60
  text "2.80mil" at 7772.01,6987.5 h60
  text "8" at 5562.59,6867.5 h60
  text "Dielectric 3" at 5972.5,6867.5 h60
  text "FR-4" at 6912.24,6867.5 h60
  text "5.60mil" at 7772.01,6867.5 h60
  text "4.2" at 8421.84,6867.5 h60
  text "9" at 5562.59,6747.5 h60
  text "Signal Layer 3" at 5972.5,6747.5 h60
  text "Copper" at 6912.24,6747.5 h60
  text "2.80mil" at 7772.01,6747.5 h60
  text "10" at 5562.59,6627.5 h60
  text "Dielectric4" at 5972.5,6627.5 h60
  text "FR-4" at 6912.24,6627.5 h60
  text "5.60mil" at 7772.01,6627.5 h60
  text "4.2" at 8421.84,6627.5 h60
  text "11" at 5562.59,6507.5 h60
  text "Signal Layer 4" at 5972.5,6507.5 h60
  text "Copper" at 6912.24,6507.5 h60
  text "2.80mil" at 7772.01,6507.5 h60
  text "12" at 5562.59,6387.5 h60
  text "Dielectric 5" at 5972.5,6387.5 h60
  text "FR-4" at 6912.24,6387.5 h60
  text "5.60mil" at 7772.01,6387.5 h60
  text "4.2" at 8421.84,6387.5 h60
  text "13" at 5562.59,6267.5 h60
  text "Signal Layer 5" at 5972.5,6267.5 h60
  text "Copper" at 6912.24,6267.5 h60
  text "2.80mil" at 7772.01,6267.5 h60
  text "14" at 5562.59,6147.5 h60
  text "Dielectric 6" at 5972.5,6147.5 h60
  text "FR-4" at 6912.24,6147.5 h60
  text "5.60mil" at 7772.01,6147.5 h60
  text "4.2" at 8421.84,6147.5 h60
  text "15" at 5562.59,6027.5 h60
  text "Signal Layer 6" at 5972.5,6027.5 h60
  text "Copper" at 6912.24,6027.5 h60
  text "2.80mil" at 7772.01,6027.5 h60
  text "16" at 5562.59,5907.5 h60
  text "Dielectric 7" at 5972.5,5907.5 h60
  text "FR-4" at 6912.24,5907.5 h60
  text "5.60mil" at 7772.01,5907.5 h60
  text "4.8" at 8421.84,5907.5 h60
  text "17" at 5562.59,5787.5 h60
  text "Bottom Layer" at 5972.5,5787.5 h60
  text "Copper" at 6912.24,5787.5 h60
  text "2.80mil" at 7772.01,5787.5 h60
  text "18" at 5562.59,5667.5 h60
  text "Bottom Solder" at 5972.5,5667.5 h60
  text "Solder Resist" at 6912.24,5667.5 h60
  text "0.40mil" at 7772.01,5667.5 h60
  text "3.5" at 8421.84,5667.5 h60
  text "19" at 5562.59,5547.5 h60
  text "Bottom Overlay" at 5972.5,5547.5 h60
  text ".Layer_Name" at 77,-858.49 h60
M13 Component Bodies Top:
  text ".Layer_Name" at 77,-858.49 h60
M14 Component Bodies Bottom:
  text ".Layer_Name" at 77,-858.49 h60
M15 Courtyards Top:
  text ".Layer_Name" at 77,-858.49 h60
M16 Courtyards Bottom:
  text ".Layer_Name" at 77,-858.49 h60
Drill Drawing:
  circle w10: c5579.85,3236.63 r27.63
  lines w10: 5552.23,2849.85 5566.04,2849.85 5566.04,2836.04 5593.67,2836.04 5593.67,2849.85 5607.48,2849.85 5607.48,2877.48 5593.67,2877.48 5593.67,2891.29 5566.04,2891.29 5566.04,2877.48 5552.23,2877.48 5552.23,2849.85 ; 5552.23,2974.17 5566.04,2974.17 5579.85,2960.36 5593.67,2974.17 5607.48,2974.17 5593.67,2987.99 5607.48,3001.8 5593.67,3001.8 5579.85,3015.61 5566.04,3001.8 5552.23,3001.8 5566.04,2987.99 5552.23,2974.17 ; 5552.23,3098.49 5566.04,3098.49 5566.04,3084.68 5593.67,3084.68 5593.67,3098.49 5607.48,3098.49 5607.48,3126.12 5593.67,3126.12 5593.67,3139.93 5566.04,3139.93 5566.04,3126.12 5552.23,3126.12 5552.23,3098.49 ; 5552.23,3333.32 5607.48,3333.32 5607.48,3388.57 5552.23,3388.57 5552.23,3333.32 ; 5552.23,3512.89 5607.48,3512.89 5579.85,3457.64 5552.23,3512.89 ; 5563.28,3104.02 5571.57,3104.02 5571.57,3095.73 5588.14,3095.73 5588.14,3104.02 5596.43,3104.02 5596.43,3120.59 5588.14,3120.59 5588.14,3128.88 5571.57,3128.88 5571.57,3120.59 5563.28,3120.59 5563.28,3104.02
  lines w12: 5502.14,2798.74 7480.16,2798.74 ; 5502.14,3793.3 7480.16,3793.3 ; 5840,2674.42 5840,3917.62 ; 6172,2674.42 6172,3917.62 ; 6808.56,2674.42 6808.56,3917.62 ; 7067.7,2674.42 7067.7,3917.62 ; 5502.14,2674.42 7480.16,2674.42 7480.16,3917.62 5502.14,3917.62 5502.14,2674.42
  text "Symbol" at 5576.73,3830.6 h72
  text "Quantity" at 5877.3,3830.6 h72
  text "Finished Hole Size" at 6209.3,3830.6 h72
  text "Plated" at 6845.86,3830.6 h72
  text "Hole Type" at 7105,3830.6 h72
  text "592" at 5877.3,3706.28 h60
  text "10.00mil (0.254mm)" at 6209.3,3706.28 h60
  text "PTH" at 6845.86,3706.28 h60
  text "Round" at 7105,3706.28 h60
  text "B" at 5551.44,3696.29 h55.25
  text "555" at 5877.3,3581.96 h60
  text "16.00mil (0.406mm)" at 6209.3,3581.96 h60
  text "PTH" at 6845.86,3581.96 h60
  text "Round" at 7105,3581.96 h60
  text "A" at 5551.44,3571.97 h55.25
  text "18" at 5877.3,3457.64 h60
  text "40.00mil (1.016mm)" at 6209.3,3457.64 h60
  text "PTH" at 6845.86,3457.64 h60
  text "Round" at 7105,3457.64 h60
  text "4" at 5877.3,3333.32 h60
  text "63.00mil (1.600mm)" at 6209.3,3333.32 h60
  text "PTH" at 6845.86,3333.32 h60
  text "Round" at 7105,3333.32 h60
  text "2" at 5877.3,3209 h60
  text "98.43mil (2.500mm)" at 6209.3,3209 h60
  text "PTH" at 6845.86,3209 h60
  text "Round" at 7105,3209 h60
  text "4" at 5877.3,3084.68 h60
  text "125.98mil (3.200mm)" at 6209.3,3084.68 h60
  text "PTH" at 6845.86,3084.68 h60
  text "Round" at 7105,3084.68 h60
  text "4" at 5877.3,2960.36 h60
  text "254.00mil (6.452mm)" at 6209.3,2960.36 h60
  text "PTH" at 6845.86,2960.36 h60
  text "Round" at 7105,2960.36 h60
  text "4" at 5877.3,2836.04 h60
  text "270.00mil (6.858mm)" at 6209.3,2836.04 h60
  text "PTH" at 6845.86,2836.04 h60
  text "Round" at 7105,2836.04 h60
  text "1183 Total" at 5877.3,2711.72 h60
  text ".Layer_Name" at 77,-858.49 h60

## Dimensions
-500,-400 to 500,-400 on M2 Board Dimensions
0,0 to 5100,0 on M2 Board Dimensions
0,0 to 0,3900 on M2 Board Dimensions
